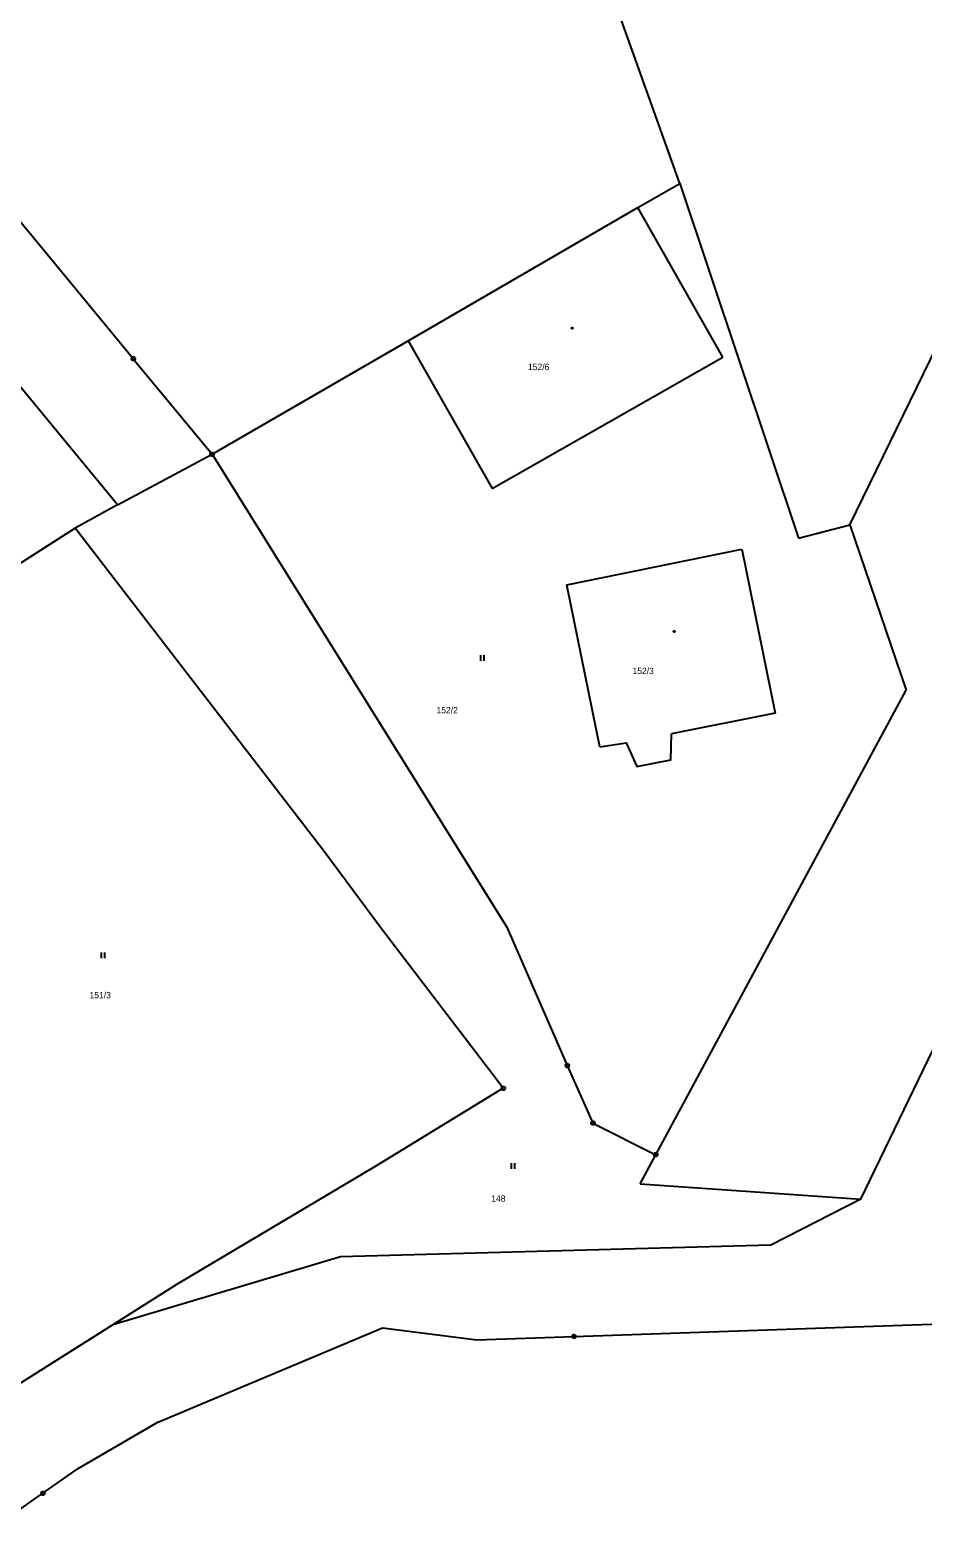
# Model space of a CAD drawing. Extents: x -871430 to -870620, y -1010094 to -1009649.
# Drawn here: x -870823.3 to -870763.8, y -1010051.6 to -1009951.2 of the extents above; entities that cross this region are included whole.
import ezdxf

# ---------------------------------------------------------------- set-up
doc = ezdxf.new("R2010")
doc.units = 0
for name, color, linetype in [('Vrstva 1', 7, 'Continuous'), ('Vrstva 2', 7, 'Continuous'), ('Vrstva 3', 7, 'Continuous'), ('Vrstva 5', 7, 'Continuous'), ('Vrstva 8', 7, 'Continuous')]:
    doc.layers.add(name, color=color, linetype=linetype)

msp = doc.modelspace()

# ---------------------------------------------------------------- linework, layer by layer
at = {"layer": 'Vrstva 1'}
for p, q in [((-870768.7, -1009984.15), (-870742.3, -1009930.08)), ((-870767.95, -1010029.06), (-870723.23, -1009936.33)), ((-870780.02, -1009961.43), (-870788.09, -1009938.81)), ((-870816.41, -1009973.1), (-870830.66, -1009955.85)), ((-870817.46, -1009982.83), (-870837.15, -1009958.98)), ((-870782.81, -1009963.04), (-870780.02, -1009961.43)), ((-870780.02, -1009961.43), (-870772.11, -1009985.04)), ((-870798.11, -1009971.9), (-870782.81, -1009963.04)), ((-870777.14, -1009972.99), (-870782.81, -1009963.04)), ((-870811.16, -1009979.46), (-870798.11, -1009971.9)), ((-870798.11, -1009971.9), (-870792.51, -1009981.74)), ((-870792.51, -1009981.74), (-870777.14, -1009972.99)), ((-870816.41, -1009973.1), (-870811.16, -1009979.46)), ((-870817.46, -1009982.83), (-870811.16, -1009979.46)), ((-870811.16, -1009979.46), (-870791.54, -1010010.95)), ((-870817.46, -1009982.83), (-870820.29, -1009984.39)), ((-870820.29, -1009984.39), (-870832.36, -1009992.09)), ((-870803.69, -1010005.92), (-870820.29, -1009984.39)), ((-870772.11, -1009985.04), (-870768.7, -1009984.15)), ((-870768.7, -1009984.15), (-870764.94, -1009995.18)), ((-870787.53, -1009988.16), (-870775.88, -1009985.79)), ((-870775.88, -1009985.79), (-870773.67, -1009996.71)), ((-870785.34, -1009998.95), (-870787.53, -1009988.16)), ((-870781.61, -1010026.1), (-870764.94, -1009995.18)), ((-870773.67, -1009996.71), (-870780.56, -1009998.08)), ((-870799.89, -1010011.06), (-870803.69, -1010005.92)), ((-870791.77, -1010021.68), (-870799.89, -1010011.06)), ((-870791.54, -1010010.95), (-870787.51, -1010020.17)), ((-870787.51, -1010020.17), (-870785.8, -1010023.99)), ((-870791.77, -1010021.68), (-870800.3, -1010026.89)), ((-870785.8, -1010023.99), (-870781.61, -1010026.1)), ((-870782.65, -1010028.03), (-870781.61, -1010026.1)), ((-870800.3, -1010026.89), (-870813.48, -1010034.73)), ((-870782.65, -1010028.03), (-870767.95, -1010029.06)), ((-870767.95, -1010029.06), (-870773.96, -1010032.13)), ((-870773.96, -1010032.13), (-870802.6, -1010032.89)), ((-870802.6, -1010032.89), (-870817.77, -1010037.43)), ((-870813.48, -1010034.73), (-870817.77, -1010037.43)), ((-870817.77, -1010037.43), (-870826, -1010042.62)), ((-870814.83, -1010043.93), (-870799.81, -1010037.63)), ((-870799.81, -1010037.63), (-870793.54, -1010038.42)), ((-870793.54, -1010038.42), (-870787.07, -1010038.2)), ((-870787.07, -1010038.2), (-870762.6, -1010037.37)), ((-870820.08, -1010047), (-870814.83, -1010043.93)), ((-870822.43, -1010048.64), (-870820.08, -1010047)), ((-870826.68, -1010051.61), (-870822.43, -1010048.64))]:
    msp.add_line(p, q, dxfattribs=at)
msp.add_lwpolyline([(-870785.34, -1009998.95), (-870783.58, -1009998.68), (-870782.88, -1010000.26), (-870780.6, -1009999.81), (-870780.56, -1009998.08)], dxfattribs=at)
at = {"layer": 'Vrstva 3'}
for p, q in [((-870793.285, -1009992.845), (-870793.285, -1009993.22)), ((-870793.035, -1009993.22), (-870793.035, -1009992.845)), ((-870818.545, -1010012.635), (-870818.545, -1010013.01)), ((-870818.295, -1010013.01), (-870818.295, -1010012.635)), ((-870791.255, -1010026.655), (-870791.255, -1010027.03)), ((-870791.005, -1010027.03), (-870791.005, -1010026.655))]:
    msp.add_line(p, q, dxfattribs=at)
at = {"layer": 'Vrstva 5'}
for points in [[(-870787.18, -1009971.018), (-870787.155, -1009971.023), (-870787.143, -1009971.045), (-870787.138, -1009971.06), (-870787.143, -1009971.082), (-870787.163, -1009971.1), (-870787.18, -1009971.102), (-870787.202, -1009971.095), (-870787.218, -1009971.08), (-870787.222, -1009971.06), (-870787.218, -1009971.038), (-870787.198, -1009971.02), (-870787.18, -1009971.018)], [(-870780.39, -1009991.218), (-870780.365, -1009991.222), (-870780.352, -1009991.245), (-870780.348, -1009991.26), (-870780.352, -1009991.282), (-870780.372, -1009991.3), (-870780.39, -1009991.302), (-870780.412, -1009991.295), (-870780.428, -1009991.28), (-870780.432, -1009991.26), (-870780.428, -1009991.238), (-870780.408, -1009991.22), (-870780.39, -1009991.218)]]:
    msp.add_lwpolyline(points, dxfattribs=at)
at = {"layer": 'Vrstva 8'}
for p, q in [((-870816.422, -1009973.1), (-870816.398, -1009973.1)), ((-870811.172, -1009979.46), (-870811.148, -1009979.46)), ((-870787.522, -1010020.17), (-870787.498, -1010020.17)), ((-870791.782, -1010021.68), (-870791.758, -1010021.68)), ((-870785.812, -1010023.99), (-870785.788, -1010023.99)), ((-870781.622, -1010026.1), (-870781.598, -1010026.1)), ((-870787.082, -1010038.2), (-870787.058, -1010038.2)), ((-870822.442, -1010048.64), (-870822.418, -1010048.64))]:
    msp.add_line(p, q, dxfattribs=at)
for points in [[(-870816.372, -1009972.98), (-870816.31, -1009973.028), (-870816.285, -1009973.1), (-870816.31, -1009973.172), (-870816.372, -1009973.22), (-870816.448, -1009973.22), (-870816.51, -1009973.172), (-870816.535, -1009973.1), (-870816.51, -1009973.028), (-870816.448, -1009972.98), (-870816.372, -1009972.98)], [(-870811.122, -1009979.34), (-870811.06, -1009979.388), (-870811.035, -1009979.46), (-870811.06, -1009979.532), (-870811.122, -1009979.58), (-870811.198, -1009979.58), (-870811.26, -1009979.532), (-870811.285, -1009979.46), (-870811.26, -1009979.388), (-870811.198, -1009979.34), (-870811.122, -1009979.34)], [(-870787.472, -1010020.05), (-870787.41, -1010020.098), (-870787.385, -1010020.17), (-870787.41, -1010020.242), (-870787.472, -1010020.29), (-870787.548, -1010020.29), (-870787.61, -1010020.242), (-870787.635, -1010020.17), (-870787.61, -1010020.098), (-870787.548, -1010020.05), (-870787.472, -1010020.05)], [(-870791.732, -1010021.56), (-870791.67, -1010021.608), (-870791.645, -1010021.68), (-870791.67, -1010021.753), (-870791.732, -1010021.8), (-870791.808, -1010021.8), (-870791.87, -1010021.753), (-870791.895, -1010021.68), (-870791.87, -1010021.608), (-870791.808, -1010021.56), (-870791.732, -1010021.56)], [(-870785.763, -1010023.87), (-870785.7, -1010023.918), (-870785.675, -1010023.99), (-870785.7, -1010024.062), (-870785.763, -1010024.11), (-870785.838, -1010024.11), (-870785.9, -1010024.062), (-870785.925, -1010023.99), (-870785.9, -1010023.918), (-870785.838, -1010023.87), (-870785.763, -1010023.87)], [(-870781.572, -1010025.98), (-870781.51, -1010026.028), (-870781.485, -1010026.1), (-870781.51, -1010026.172), (-870781.572, -1010026.22), (-870781.648, -1010026.22), (-870781.71, -1010026.172), (-870781.735, -1010026.1), (-870781.71, -1010026.028), (-870781.648, -1010025.98), (-870781.572, -1010025.98)], [(-870787.032, -1010038.08), (-870786.97, -1010038.128), (-870786.945, -1010038.2), (-870786.97, -1010038.272), (-870787.032, -1010038.32), (-870787.107, -1010038.32), (-870787.17, -1010038.272), (-870787.195, -1010038.2), (-870787.17, -1010038.128), (-870787.107, -1010038.08), (-870787.032, -1010038.08)], [(-870822.393, -1010048.52), (-870822.33, -1010048.568), (-870822.305, -1010048.64), (-870822.33, -1010048.712), (-870822.393, -1010048.76), (-870822.468, -1010048.76), (-870822.53, -1010048.712), (-870822.555, -1010048.64), (-870822.53, -1010048.568), (-870822.468, -1010048.52), (-870822.393, -1010048.52)]]:
    msp.add_lwpolyline(points, dxfattribs=at)

# ---------------------------------------------------------------- texts
at = {"layer": 'Vrstva 2'}
for s, p in [('152/6', (-870790.122, -1009973.86)), ('152/3', (-870783.162, -1009994.1)), ('152/2', (-870796.212, -1009996.71)), ('151/3', (-870819.323, -1010015.69)), ('148', (-870792.572, -1010029.23))]:
    msp.add_text(s, height=0.425, dxfattribs=at).set_placement(p)

doc.saveas('drawing.dxf')
